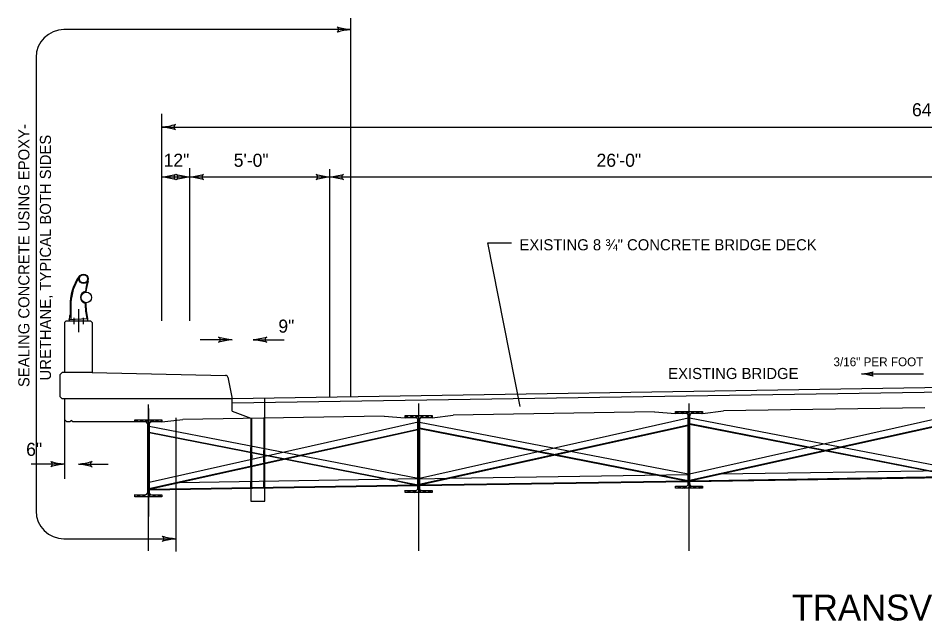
# Model space of a CAD drawing. Extents: x 10803 to 14007, y 6159 to 7440.
# Drawn here: x 13618.12 to 13650.54, y 6324.31 to 6345.88 of the extents above; entities that cross this region are included whole.
import ezdxf

# ---------------------------------------------------------------- set-up
doc = ezdxf.new("R2010")
doc.units = 0
for name, color, linetype in [('BR_X_Rail_Object', 7, 'Continuous'), ('BR_X_Slab_Const_Joint', 7, 'Continuous'), ('BR_X_Slab_Object', 7, 'Continuous'), ('Default', 7, 'Continuous')]:
    doc.layers.add(name, color=color, linetype=linetype)

# ---------------------------------------------------------------- blocks, each defined once
blk = doc.blocks.new('LT2')
at = {"layer": 'Default'}
blk.add_line((-0.163, 0.031), (-0.163, 0.031), dxfattribs=at)
for centre, start, end in [((0.147, 1.218), 255.3829, 263.1374), ((0.147, -1.218), 96.8626, 104.6171)]:
    blk.add_arc(centre, 1.227, start, end, dxfattribs=at)
blk.add_ellipse((-0.185, 0), major_axis=(0.0415, 0), ratio=0.873734, start_param=5.258637, end_param=7.300638, dxfattribs=at)

msp = doc.modelspace()

# ---------------------------------------------------------------- linework, layer by layer
at = {"layer": 'BR_X_Rail_Object'}
for p, q in [((13620.318, 6336.638), (13620.299, 6336.648)), ((13620.626, 6336.472), (13620.607, 6336.478)), ((13619.976, 6335.582), (13619.976, 6335.265)), ((13620.002, 6335.584), (13620.002, 6335.098)), ((13619.943, 6335.094), (13620.606, 6335.133)), ((13619.943, 6335.094), (13619.943, 6335.051)), ((13620.606, 6335.133), (13620.606, 6335.051))]:
    msp.add_line(p, q, dxfattribs=at)
for centre, radius in [((13620.458, 6336.551), 0.166), ((13620.458, 6336.551), 0.146), ((13620.559, 6335.885), 0.187)]:
    msp.add_circle(centre, radius, dxfattribs=at)
for centre, radius, start, end in [((13621.893, 6335.584), 1.916, 146.2879, 180.0713), ((13621.893, 6335.584), 1.89, 151.3488, 180.0713), ((13620.269, 6336.471), 0.0394, 22.735, 151.3488), ((13622.677, 6335.841), 2.165, 162.8878, 173.1781), ((13622.677, 6335.841), 2.146, 162.8878, 173.8469), ((13620.559, 6335.885), 0.213, 98.8055, 259.1055), ((13622.71, 6335.635), 2.192, 178.9792, 193.4258), ((13622.71, 6335.635), 2.165, 178.3406, 193.4258), ((13619.477, 6335.271), 0.499, 339.2463, 359.3787)]:
    msp.add_arc(centre, radius, start, end, dxfattribs=at)
at = {"layer": 'BR_X_Slab_Const_Joint'}
for p, q in [((13620.774, 6333.198), (13619.774, 6333.198)), ((13625.774, 6332.26), (13619.774, 6332.26))]:
    msp.add_line(p, q, dxfattribs=at)
at = {"layer": 'BR_X_Slab_Object'}
for p, q in [((13619.774, 6334.989), (13619.837, 6335.051)), ((13619.837, 6335.051), (13620.712, 6335.051)), ((13620.774, 6334.989), (13620.712, 6335.051)), ((13619.774, 6334.989), (13619.774, 6333.198)), ((13620.774, 6334.989), (13620.774, 6333.198)), ((13619.691, 6333.198), (13619.608, 6333.114)), ((13619.608, 6333.114), (13619.608, 6332.344)), ((13619.774, 6333.198), (13619.691, 6333.198)), ((13620.774, 6333.198), (13625.541, 6333.095)), ((13625.621, 6333.028), (13625.774, 6332.26)), ((13651.774, 6332.666), (13625.774, 6332.26)), ((13651.774, 6332.508), (13625.774, 6332.101)), ((13619.608, 6332.344), (13619.691, 6332.26)), ((13619.774, 6332.26), (13619.691, 6332.26)), ((13619.774, 6332.26), (13619.774, 6331.519)), ((13625.774, 6332.101), (13625.774, 6332.26)), ((13640.881, 6331.788), (13633.672, 6331.675)), ((13640.881, 6331.788), (13641.631, 6331.734)), ((13642.589, 6331.734), (13643.339, 6331.826)), ((13650.545, 6331.939), (13643.339, 6331.826)), ((13619.858, 6331.436), (13619.774, 6331.519)), ((13623.257, 6331.432), (13624.006, 6331.524)), ((13631.214, 6331.637), (13624.006, 6331.524)), ((13631.214, 6331.637), (13631.964, 6331.583)), ((13632.923, 6331.583), (13633.672, 6331.675)), ((13619.984, 6331.436), (13619.858, 6331.436)), ((13622.555, 6331.436), (13620.066, 6331.436))]:
    msp.add_line(p, q, dxfattribs=at)
for centre, radius, start, end in [((13625.539, 6333.012), 0.0833, 11.3099, 88.7673), ((13620.024, 6331.436), 0.0417, 359.9982, 180)]:
    msp.add_arc(centre, radius, start, end, dxfattribs=at)
at = {"layer": 'Default'}
for p, q in [((13630.014, 6332.315), (13630.014, 6345.877)), ((13630.014, 6345.468), (13619.76, 6345.468)), ((13629.526, 6345.561), (13629.525, 6345.561)), ((13618.76, 6344.468), (13618.76, 6328.251)), ((13623.264, 6335.044), (13623.264, 6342.456)), ((13623.264, 6341.979), (13680.285, 6341.979)), ((13623.752, 6341.886), (13623.753, 6341.886)), ((13623.264, 6340.196), (13624.264, 6340.196)), ((13623.776, 6340.289), (13623.775, 6340.289)), ((13624.264, 6335.044), (13624.264, 6340.514)), ((13624.264, 6340.196), (13629.264, 6340.196)), ((13628.776, 6340.289), (13628.775, 6340.289)), ((13629.264, 6332.315), (13629.264, 6340.469)), ((13629.264, 6340.196), (13651.774, 6340.196)), ((13623.752, 6340.103), (13623.753, 6340.103)), ((13624.752, 6340.103), (13624.753, 6340.103)), ((13629.752, 6340.103), (13629.753, 6340.103)), ((13636.072, 6331.982), (13634.913, 6337.838)), ((13634.913, 6337.838), (13635.759, 6337.838)), ((13620.274, 6335.463), (13620.274, 6334.64)), ((13620.107, 6335.16), (13620.107, 6334.927)), ((13620.442, 6335.16), (13620.442, 6334.933)), ((13625.774, 6334.374), (13624.632, 6334.374)), ((13625.286, 6334.467), (13625.285, 6334.467)), ((13626.524, 6334.374), (13627.629, 6334.374)), ((13627.012, 6334.282), (13627.013, 6334.282)), ((13648.285, 6333.149), (13650.491, 6333.149)), ((13625.774, 6331.814), (13625.774, 6332.101)), ((13626.94, 6330.4), (13626.94, 6332.279)), ((13632.441, 6332.091), (13632.441, 6326.816)), ((13642.11, 6332.091), (13642.11, 6328.502)), ((13622.774, 6332.05), (13622.774, 6326.816)), ((13622.778, 6331.912), (13622.778, 6328.053)), ((13625.774, 6331.814), (13626.44, 6331.562)), ((13632.443, 6332.05), (13632.443, 6328.19)), ((13641.631, 6331.734), (13641.631, 6331.807)), ((13641.631, 6331.807), (13642.589, 6331.807)), ((13641.631, 6331.745), (13641.693, 6331.807)), ((13641.676, 6331.734), (13641.749, 6331.807)), ((13641.804, 6331.734), (13641.877, 6331.807)), ((13641.86, 6331.734), (13641.933, 6331.807)), ((13641.988, 6331.734), (13642.06, 6331.807)), ((13642.035, 6331.725), (13642.117, 6331.807)), ((13642.086, 6331.649), (13642.244, 6331.807)), ((13642.228, 6331.734), (13642.301, 6331.807)), ((13642.355, 6331.734), (13642.428, 6331.807)), ((13642.412, 6331.734), (13642.485, 6331.807)), ((13642.539, 6331.734), (13642.589, 6331.784)), ((13642.589, 6331.807), (13642.589, 6331.734)), ((13619.774, 6331.519), (13619.774, 6329.4)), ((13622.298, 6331.432), (13622.298, 6331.505)), ((13622.298, 6331.505), (13623.257, 6331.505)), ((13622.298, 6331.443), (13622.36, 6331.505)), ((13622.344, 6331.432), (13622.417, 6331.505)), ((13622.471, 6331.432), (13622.544, 6331.505)), ((13622.528, 6331.432), (13622.601, 6331.505)), ((13622.655, 6331.432), (13622.728, 6331.505)), ((13622.703, 6331.423), (13622.785, 6331.505)), ((13622.753, 6331.347), (13622.912, 6331.505)), ((13622.895, 6331.432), (13622.968, 6331.505)), ((13623.023, 6331.432), (13623.096, 6331.505)), ((13623.079, 6331.432), (13623.152, 6331.505)), ((13623.207, 6331.432), (13623.257, 6331.482)), ((13623.257, 6331.505), (13623.257, 6331.432)), ((13623.764, 6331.574), (13623.764, 6326.796)), ((13626.44, 6331.562), (13626.44, 6330.512)), ((13626.472, 6330.505), (13626.472, 6331.563)), ((13626.909, 6331.57), (13626.909, 6330.407)), ((13631.964, 6331.583), (13631.964, 6331.656)), ((13631.964, 6331.656), (13632.923, 6331.656)), ((13631.964, 6331.594), (13632.026, 6331.656)), ((13632.336, 6331.583), (13631.964, 6331.583)), ((13632.01, 6331.583), (13632.083, 6331.656)), ((13632.137, 6331.583), (13632.21, 6331.656)), ((13632.194, 6331.583), (13632.267, 6331.656)), ((13632.321, 6331.583), (13632.394, 6331.656)), ((13632.336, 6331.583), (13632.336, 6331.583)), ((13632.368, 6331.574), (13632.45, 6331.656)), ((13632.419, 6331.498), (13632.578, 6331.656)), ((13632.419, 6329.062), (13632.419, 6331.5)), ((13632.419, 6331.441), (13632.468, 6331.489)), ((13642.086, 6331.571), (13632.468, 6329.412)), ((13632.468, 6331.5), (13632.468, 6329.062)), ((13632.923, 6331.583), (13632.551, 6331.583)), ((13632.561, 6331.583), (13632.634, 6331.656)), ((13632.689, 6331.583), (13632.762, 6331.656)), ((13632.745, 6331.583), (13632.818, 6331.656)), ((13632.872, 6331.583), (13632.923, 6331.633)), ((13632.923, 6331.656), (13632.923, 6331.583)), ((13642.003, 6331.734), (13641.631, 6331.734)), ((13642.003, 6331.734), (13642.003, 6331.734)), ((13642.086, 6329.213), (13642.086, 6331.651)), ((13642.086, 6331.592), (13642.134, 6331.64)), ((13642.086, 6331.465), (13642.134, 6331.513)), ((13642.086, 6331.408), (13642.134, 6331.457)), ((13642.13, 6329.351), (13651.748, 6331.479)), ((13651.753, 6331.723), (13642.134, 6329.564)), ((13642.134, 6331.651), (13642.134, 6329.213)), ((13651.753, 6329.713), (13642.134, 6331.568)), ((13642.134, 6329.33), (13651.753, 6331.458)), ((13642.589, 6331.734), (13642.218, 6331.734)), ((13622.67, 6331.432), (13622.298, 6331.432)), ((13622.67, 6331.432), (13622.67, 6331.432)), ((13622.753, 6328.911), (13622.753, 6331.349)), ((13622.753, 6331.29), (13622.802, 6331.338)), ((13622.753, 6331.163), (13622.802, 6331.211)), ((13622.753, 6331.106), (13622.802, 6331.155)), ((13622.797, 6329.049), (13632.416, 6331.177)), ((13632.42, 6331.42), (13622.802, 6329.261)), ((13622.802, 6331.349), (13622.802, 6328.911)), ((13632.42, 6329.411), (13622.802, 6331.265)), ((13622.802, 6329.028), (13632.42, 6331.156)), ((13623.257, 6331.432), (13622.885, 6331.432)), ((13632.419, 6331.314), (13632.468, 6331.362)), ((13632.419, 6331.257), (13632.468, 6331.306)), ((13632.419, 6331.13), (13632.468, 6331.178)), ((13632.419, 6331.073), (13632.468, 6331.122)), ((13632.463, 6329.2), (13642.081, 6331.328)), ((13642.086, 6329.562), (13632.468, 6331.416)), ((13632.468, 6329.179), (13642.086, 6331.307)), ((13642.086, 6329.304), (13632.468, 6331.188)), ((13642.086, 6329.325), (13632.472, 6331.208)), ((13642.086, 6331.281), (13642.134, 6331.329)), ((13642.086, 6331.224), (13642.134, 6331.273)), ((13642.086, 6331.097), (13642.134, 6331.145)), ((13651.753, 6329.455), (13642.134, 6331.339)), ((13651.753, 6329.476), (13642.138, 6331.359)), ((13622.753, 6330.979), (13622.802, 6331.027)), ((13622.753, 6330.922), (13622.802, 6330.971)), ((13622.753, 6330.795), (13622.802, 6330.843)), ((13632.42, 6329.153), (13622.802, 6331.037)), ((13632.42, 6329.174), (13622.806, 6331.057)), ((13632.419, 6330.946), (13632.468, 6330.994)), ((13632.419, 6330.889), (13632.468, 6330.938)), ((13632.419, 6330.762), (13632.468, 6330.811)), ((13642.086, 6331.041), (13642.134, 6331.089)), ((13642.086, 6330.913), (13642.134, 6330.962)), ((13642.086, 6330.857), (13642.134, 6330.905)), ((13642.108, 6330.872), (13642.108, 6326.816)), ((13622.753, 6330.738), (13622.802, 6330.787)), ((13622.753, 6330.611), (13622.802, 6330.66)), ((13622.753, 6330.555), (13622.802, 6330.603)), ((13622.753, 6330.427), (13622.802, 6330.476)), ((13626.44, 6330.254), (13626.44, 6330.512)), ((13626.472, 6330.247), (13626.472, 6330.505)), ((13632.419, 6330.706), (13632.468, 6330.754)), ((13632.419, 6330.578), (13632.468, 6330.627)), ((13632.419, 6330.522), (13632.468, 6330.57)), ((13642.086, 6330.729), (13642.134, 6330.778)), ((13642.086, 6330.673), (13642.134, 6330.721)), ((13642.086, 6330.546), (13642.134, 6330.594)), ((13642.086, 6330.489), (13642.134, 6330.537)), ((13622.753, 6330.371), (13622.802, 6330.419)), ((13622.753, 6330.244), (13622.802, 6330.292)), ((13622.753, 6330.187), (13622.802, 6330.235)), ((13626.44, 6330.128), (13626.44, 6330.254)), ((13626.472, 6330.247), (13626.472, 6330.136)), ((13626.909, 6329.988), (13626.909, 6330.407)), ((13626.94, 6329.996), (13626.94, 6330.4)), ((13632.419, 6330.395), (13632.468, 6330.443)), ((13632.419, 6330.338), (13632.468, 6330.386)), ((13632.419, 6330.211), (13632.468, 6330.259)), ((13632.419, 6330.154), (13632.468, 6330.202)), ((13642.086, 6330.362), (13642.134, 6330.41)), ((13642.086, 6330.305), (13642.134, 6330.354)), ((13642.086, 6330.178), (13642.134, 6330.226)), ((13642.086, 6330.121), (13642.134, 6330.17)), ((13619.774, 6329.922), (13618.591, 6329.922)), ((13619.286, 6330.015), (13619.285, 6330.015)), ((13620.274, 6329.922), (13621.339, 6329.922)), ((13620.762, 6329.829), (13620.763, 6329.829)), ((13622.753, 6330.06), (13622.802, 6330.108)), ((13622.753, 6330.003), (13622.802, 6330.051)), ((13622.753, 6329.876), (13622.802, 6329.924)), ((13622.753, 6329.819), (13622.802, 6329.868)), ((13626.44, 6329.868), (13626.44, 6330.128)), ((13626.44, 6329.868), (13626.44, 6329.309)), ((13626.472, 6329.876), (13626.472, 6330.136)), ((13626.472, 6329.309), (13626.472, 6329.876)), ((13626.909, 6329.988), (13626.909, 6329.316)), ((13626.94, 6329.316), (13626.94, 6329.996)), ((13632.419, 6330.027), (13632.468, 6330.075)), ((13632.419, 6329.97), (13632.468, 6330.019)), ((13632.419, 6329.843), (13632.468, 6329.891)), ((13632.419, 6329.786), (13632.468, 6329.835)), ((13642.086, 6329.994), (13642.134, 6330.042)), ((13642.086, 6329.937), (13642.134, 6329.986)), ((13642.086, 6329.81), (13642.134, 6329.859)), ((13622.753, 6329.692), (13622.802, 6329.74)), ((13622.753, 6329.635), (13622.802, 6329.684)), ((13622.753, 6329.508), (13622.802, 6329.556)), ((13622.753, 6329.452), (13622.802, 6329.5)), ((13632.419, 6329.659), (13632.468, 6329.707)), ((13632.419, 6329.603), (13632.468, 6329.651)), ((13632.419, 6329.475), (13632.468, 6329.524)), ((13633.553, 6329.419), (13642.086, 6329.554)), ((13642.086, 6329.754), (13642.134, 6329.802)), ((13642.086, 6329.626), (13642.134, 6329.675)), ((13642.086, 6329.57), (13642.134, 6329.618)), ((13642.086, 6329.443), (13642.134, 6329.491)), ((13643.22, 6329.57), (13651.753, 6329.705)), ((13622.753, 6329.324), (13622.802, 6329.373)), ((13622.753, 6329.268), (13622.802, 6329.316)), ((13622.753, 6329.14), (13622.802, 6329.189)), ((13622.802, 6329.027), (13632.42, 6329.179)), ((13623.887, 6329.268), (13632.42, 6329.403)), ((13626.44, 6329.059), (13626.44, 6329.309)), ((13626.472, 6329.059), (13626.472, 6329.309)), ((13626.909, 6329.066), (13626.909, 6329.316)), ((13626.94, 6329.066), (13626.94, 6329.316)), ((13631.376, 6329.386), (13632.419, 6329.152)), ((13632.419, 6329.419), (13632.468, 6329.467)), ((13632.419, 6329.291), (13632.468, 6329.34)), ((13632.419, 6329.235), (13632.468, 6329.283)), ((13632.468, 6329.402), (13633.553, 6329.42)), ((13632.468, 6329.178), (13642.086, 6329.33)), ((13632.471, 6329.152), (13642.086, 6329.304)), ((13642.084, 6329.201), (13642.134, 6329.25)), ((13642.086, 6329.386), (13642.134, 6329.434)), ((13642.086, 6329.259), (13642.134, 6329.307)), ((13642.134, 6329.33), (13651.753, 6329.481)), ((13642.138, 6329.303), (13651.753, 6329.455)), ((13622.736, 6328.755), (13622.831, 6328.85)), ((13622.752, 6328.898), (13622.802, 6328.948)), ((13622.753, 6329.084), (13622.802, 6329.132)), ((13622.753, 6328.957), (13622.802, 6329.005)), ((13622.805, 6329.001), (13632.42, 6329.153)), ((13626.44, 6329.059), (13626.44, 6328.592)), ((13626.94, 6328.592), (13626.94, 6329.066)), ((13631.964, 6328.906), (13631.964, 6328.986)), ((13631.964, 6328.979), (13632.336, 6328.979)), ((13631.964, 6328.964), (13631.979, 6328.979)), ((13632.923, 6328.906), (13631.964, 6328.906)), ((13632.034, 6328.906), (13632.107, 6328.979)), ((13632.09, 6328.906), (13632.163, 6328.979)), ((13632.218, 6328.906), (13632.291, 6328.979)), ((13632.274, 6328.906), (13632.351, 6328.983)), ((13632.402, 6328.906), (13632.497, 6329.001)), ((13632.418, 6329.049), (13632.468, 6329.099)), ((13632.419, 6329.108), (13632.468, 6329.156)), ((13632.458, 6328.906), (13632.534, 6328.982)), ((13632.551, 6328.979), (13632.923, 6328.979)), ((13632.585, 6328.906), (13632.658, 6328.979)), ((13632.642, 6328.906), (13632.715, 6328.979)), ((13632.769, 6328.906), (13632.842, 6328.979)), ((13632.826, 6328.906), (13632.899, 6328.979)), ((13632.923, 6328.979), (13632.923, 6328.906)), ((13641.631, 6329.057), (13641.631, 6329.137)), ((13641.631, 6329.13), (13642.003, 6329.13)), ((13641.631, 6329.115), (13641.646, 6329.13)), ((13642.589, 6329.057), (13641.631, 6329.057)), ((13641.7, 6329.057), (13641.773, 6329.13)), ((13641.757, 6329.057), (13641.83, 6329.13)), ((13641.884, 6329.057), (13641.957, 6329.13)), ((13641.941, 6329.057), (13642.017, 6329.134)), ((13642.068, 6329.057), (13642.163, 6329.152)), ((13642.125, 6329.057), (13642.201, 6329.133)), ((13642.218, 6329.13), (13642.589, 6329.13)), ((13642.252, 6329.057), (13642.325, 6329.13)), ((13642.309, 6329.057), (13642.382, 6329.13)), ((13642.436, 6329.057), (13642.509, 6329.13)), ((13642.492, 6329.057), (13642.565, 6329.13)), ((13642.589, 6329.13), (13642.589, 6329.057)), ((13622.298, 6328.755), (13622.298, 6328.835)), ((13622.298, 6328.828), (13622.67, 6328.828)), ((13622.298, 6328.813), (13622.314, 6328.828)), ((13623.257, 6328.755), (13622.298, 6328.755)), ((13622.368, 6328.755), (13622.441, 6328.828)), ((13622.425, 6328.755), (13622.497, 6328.828)), ((13622.552, 6328.755), (13622.625, 6328.828)), ((13622.608, 6328.755), (13622.685, 6328.832)), ((13622.792, 6328.755), (13622.868, 6328.831)), ((13622.885, 6328.828), (13623.257, 6328.828)), ((13622.92, 6328.755), (13622.992, 6328.828)), ((13622.976, 6328.755), (13623.049, 6328.828)), ((13623.103, 6328.755), (13623.176, 6328.828)), ((13623.16, 6328.755), (13623.233, 6328.828)), ((13623.257, 6328.828), (13623.257, 6328.755)), ((13626.44, 6328.592), (13626.94, 6328.592)), ((13619.76, 6327.251), (13623.764, 6327.251)), ((13623.276, 6327.344), (13623.275, 6327.344))]:
    msp.add_line(p, q, dxfattribs=at)
for centre, radius, start, end in [((13619.76, 6344.468), 1, 90, 180), ((13630.454, 6349.122), 3.68, 255.3829, 263.1374), ((13630.454, 6341.815), 3.68, 96.8626, 104.6171), ((13622.824, 6345.633), 3.68, 276.8626, 284.6171), ((13622.824, 6338.325), 3.68, 75.3829, 83.1374), ((13622.824, 6343.85), 3.68, 276.8626, 284.6171), ((13622.824, 6336.542), 3.68, 75.3829, 83.1374), ((13624.704, 6343.85), 3.68, 255.3829, 263.1374), ((13624.704, 6336.542), 3.68, 96.8626, 104.6171), ((13623.824, 6343.85), 3.68, 276.8626, 284.6171), ((13623.824, 6336.542), 3.68, 75.3829, 83.1374), ((13629.704, 6343.85), 3.68, 255.3829, 263.1374), ((13629.704, 6336.542), 3.68, 96.8626, 104.6171), ((13628.824, 6343.85), 3.68, 276.8626, 284.6171), ((13628.824, 6336.542), 3.68, 75.3829, 83.1374), ((13626.214, 6338.028), 3.68, 255.3829, 263.1374), ((13626.214, 6330.72), 3.68, 96.8626, 104.6171), ((13626.084, 6338.028), 3.68, 276.8626, 284.6171), ((13626.084, 6330.72), 3.68, 75.3829, 83.1374), ((13632.336, 6331.5), 0.0833, 0, 90), ((13632.551, 6331.5), 0.0833, 90, 180), ((13642.003, 6331.651), 0.0833, 0, 90), ((13642.218, 6331.651), 0.0833, 90, 180), ((13622.67, 6331.349), 0.0833, 0, 90), ((13622.885, 6331.349), 0.0833, 90, 180), ((13620.214, 6333.576), 3.68, 255.3829, 263.1374), ((13620.214, 6326.268), 3.68, 96.8626, 104.6171), ((13619.834, 6333.576), 3.68, 276.8626, 284.6171), ((13619.834, 6326.268), 3.68, 75.3829, 83.1374), ((13642.003, 6329.213), 0.0833, 270, 360), ((13642.218, 6329.213), 0.0833, 180, 270), ((13622.67, 6328.911), 0.0833, 270, 360), ((13622.885, 6328.911), 0.0833, 180, 270), ((13632.336, 6329.062), 0.0833, 270, 360), ((13632.551, 6329.062), 0.0833, 180, 270), ((13619.76, 6328.251), 1, 180, 270), ((13624.204, 6330.905), 3.68, 255.3829, 263.1374), ((13624.204, 6323.597), 3.68, 96.8626, 104.6171)]:
    msp.add_arc(centre, radius, start, end, dxfattribs=at)
for centre, major_axis in [((13629.46, 6345.469), (0.125, 0)), ((13623.818, 6341.979), (-0.125, 0)), ((13623.818, 6340.196), (-0.125, 0)), ((13623.71, 6340.196), (0.125, 0)), ((13624.818, 6340.196), (-0.125, 0)), ((13628.71, 6340.196), (0.125, 0)), ((13629.818, 6340.196), (-0.125, 0)), ((13625.22, 6334.375), (0.125, 0)), ((13627.078, 6334.374), (-0.125, 0)), ((13619.221, 6329.922), (0.125, 0)), ((13620.828, 6329.922), (-0.125, 0)), ((13623.21, 6327.251), (0.125, 0))]:
    msp.add_ellipse(centre, major_axis=major_axis, ratio=0.873734, start_param=5.258637, end_param=7.300638, dxfattribs=at)

# ---------------------------------------------------------------- block references
at = {"layer": 'Default', "xscale": 2.499995, "yscale": 2.499995, "rotation": 180}
msp.add_blockref('LT2', (13648.285, 6333.149), dxfattribs=at)

# ---------------------------------------------------------------- texts
at = {"layer": 'Default'}
for s, height, p in [('64\'-0" C/C', 0.468, (13650.086, 6342.365)), ('12"', 0.468, (13623.324, 6340.559)), ('5\'-0"', 0.468, (13625.831, 6340.559)), ('26\'-0"', 0.468, (13638.805, 6340.559)), ('EXISTING 8 ¾" CONCRETE BRIDGE DECK', 0.39687, (13636.049, 6337.571)), ('9"', 0.468, (13627.427, 6334.624)), ('3/16" PER FOOT', 0.3125, (13647.277, 6333.426)), ('EXISTING BRIDGE', 0.39687, (13641.367, 6332.966)), ('6"', 0.468, (13618.408, 6330.217)), ('TRANSVERSE SECTION', 0.92604, (13645.787, 6324.328))]:
    msp.add_text(s, height=height, dxfattribs=at).set_placement(p)
for s, p in [('SEALING CONCRETE USING EPOXY-', (13618.524, 6332.679)), ('URETHANE, TYPICAL BOTH SIDES', (13619.296, 6332.916))]:
    msp.add_text(s, height=0.39687, rotation=90, dxfattribs=at).set_placement(p)

doc.saveas('drawing.dxf')
